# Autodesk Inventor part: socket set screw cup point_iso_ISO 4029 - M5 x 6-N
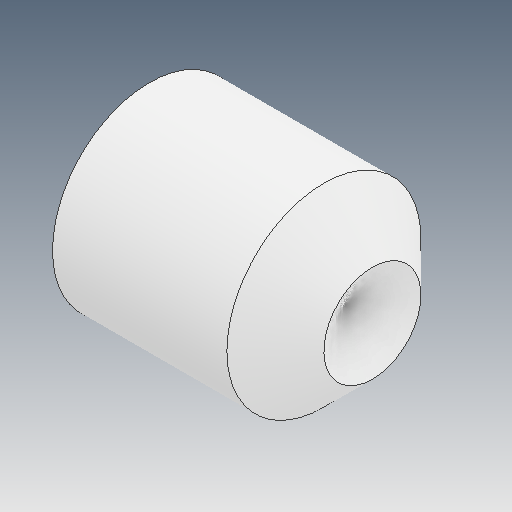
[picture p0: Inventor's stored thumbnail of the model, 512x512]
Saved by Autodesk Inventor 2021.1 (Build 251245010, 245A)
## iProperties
Created: 2021-05
Part Number: socket set screw cup point_iso_ISO 4029 - M5 x 6-N
Material: Ogólny
Document SubType Name: Modeling
Designer: user
Density: 1 g/cm^3
Appearance: Domyślna
Author: user
Revision Number: ÈÎºÎ
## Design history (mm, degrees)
feature "ÊäÈë1"
node "Bryła1"
